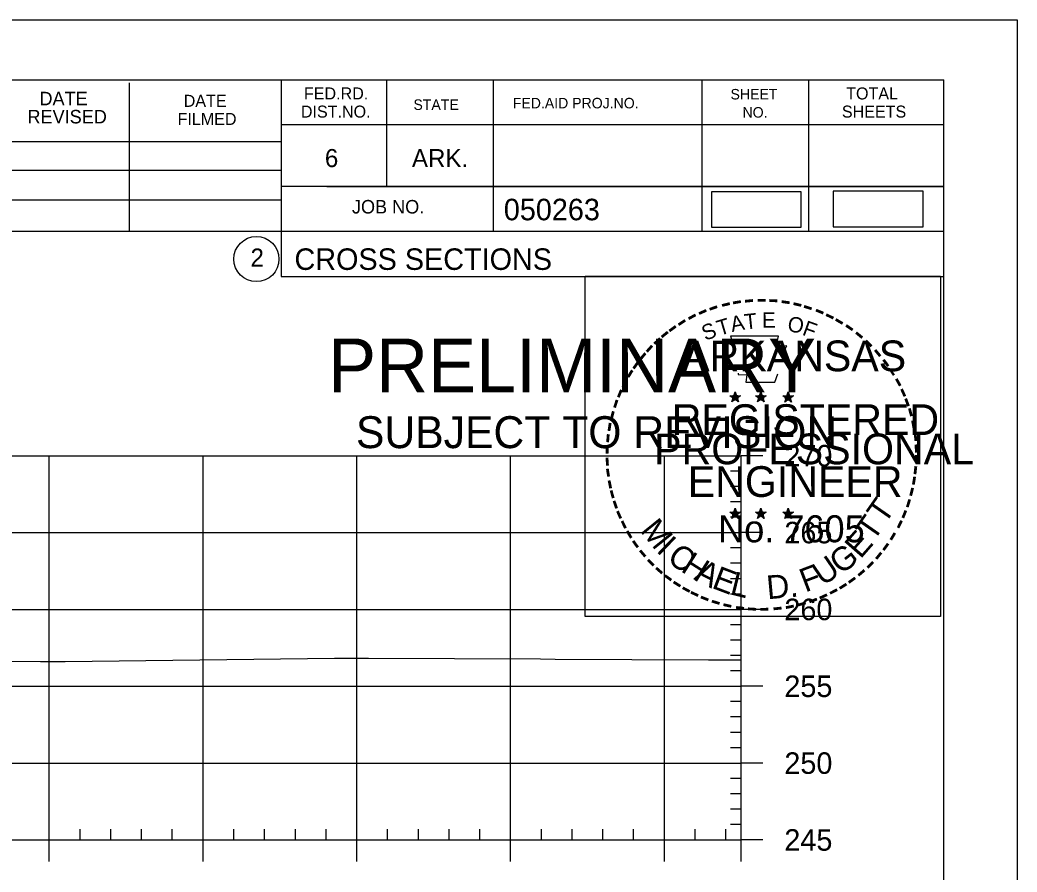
# Model space of a CAD drawing. Extents: x 1365647 to 1367999, y 387113 to 400173.
# Drawn here: x 1365992.2 to 1366057, y 387317.3 to 387372.7 of the extents above; entities that cross this region are included whole.
import ezdxf

# ---------------------------------------------------------------- set-up
doc = ezdxf.new("R2010")
doc.units = 0
for name, color, linetype in [('R_Axis', 7, 'Continuous'), ('R_Axis Annot', 7, 'Continuous'), ('R_Border', 7, 'Continuous'), ('R_Border PE', 7, 'Continuous'), ('R_Border Prem', 7, 'Continuous'), ('R_Detour', 7, 'Continuous'), ('R_Exist Surface', 7, 'Continuous'), ('R_Grid', 7, 'Continuous'), ('R_No Plot', 7, 'Continuous')]:
    doc.layers.add(name, color=color, linetype=linetype)

msp = doc.modelspace()

# ---------------------------------------------------------------- linework, layer by layer
at = {"layer": 'R_Axis'}
for p, q in [((1366039.095, 387319.379), (1366039.095, 387344.379)), ((1366040.495, 387344.379), (1366039.095, 387344.379)), ((1366039.095, 387343.379), (1366038.395, 387343.379)), ((1366039.095, 387342.379), (1366038.395, 387342.379)), ((1366039.095, 387341.379), (1366038.395, 387341.379)), ((1366039.095, 387340.379), (1366038.395, 387340.379)), ((1366040.495, 387339.379), (1366039.095, 387339.379)), ((1366039.095, 387338.379), (1366038.395, 387338.379)), ((1366039.095, 387337.379), (1366038.395, 387337.379)), ((1366039.095, 387336.379), (1366038.395, 387336.379)), ((1366039.095, 387335.379), (1366038.395, 387335.379)), ((1366040.495, 387334.379), (1366039.095, 387334.379)), ((1366039.095, 387333.379), (1366038.395, 387333.379)), ((1366039.095, 387332.379), (1366038.395, 387332.379)), ((1366039.095, 387331.379), (1366038.395, 387331.379)), ((1366039.095, 387330.379), (1366038.395, 387330.379)), ((1366040.495, 387329.379), (1366039.095, 387329.379)), ((1366039.095, 387328.379), (1366038.395, 387328.379)), ((1366039.095, 387327.379), (1366038.395, 387327.379)), ((1366039.095, 387326.379), (1366038.395, 387326.379)), ((1366039.095, 387325.379), (1366038.395, 387325.379)), ((1366040.495, 387324.379), (1366039.095, 387324.379)), ((1366039.095, 387323.379), (1366038.395, 387323.379)), ((1366039.095, 387322.379), (1366038.395, 387322.379)), ((1366039.095, 387321.379), (1366038.395, 387321.379)), ((1365996.095, 387319.379), (1365996.095, 387320.079)), ((1365998.095, 387319.379), (1365998.095, 387320.079)), ((1366000.095, 387319.379), (1366000.095, 387320.079)), ((1366002.095, 387319.379), (1366002.095, 387320.079)), ((1366006.095, 387319.379), (1366006.095, 387320.079)), ((1366008.095, 387319.379), (1366008.095, 387320.079)), ((1366010.095, 387319.379), (1366010.095, 387320.079)), ((1366012.095, 387319.379), (1366012.095, 387320.079)), ((1366016.095, 387319.379), (1366016.095, 387320.079)), ((1366018.095, 387319.379), (1366018.095, 387320.079)), ((1366020.095, 387319.379), (1366020.095, 387320.079)), ((1366022.095, 387319.379), (1366022.095, 387320.079)), ((1366026.095, 387319.379), (1366026.095, 387320.079)), ((1366028.095, 387319.379), (1366028.095, 387320.079)), ((1366030.095, 387319.379), (1366030.095, 387320.079)), ((1366032.095, 387319.379), (1366032.095, 387320.079)), ((1366036.095, 387319.379), (1366036.095, 387320.079)), ((1366038.095, 387319.379), (1366038.095, 387320.079)), ((1366039.095, 387320.379), (1366038.395, 387320.379)), ((1365749.095, 387319.379), (1366039.095, 387319.379)), ((1365994.095, 387317.979), (1365994.095, 387319.379)), ((1366004.095, 387317.979), (1366004.095, 387319.379)), ((1366014.095, 387317.979), (1366014.095, 387319.379)), ((1366024.095, 387317.979), (1366024.095, 387319.379)), ((1366034.095, 387317.979), (1366034.095, 387319.379)), ((1366039.095, 387317.979), (1366039.095, 387319.379)), ((1366040.495, 387319.379), (1366039.095, 387319.379))]:
    msp.add_line(p, q, dxfattribs=at)
at = {"layer": 'R_Border'}
for p, q in [((1365736.095, 387368.839), (1366052.275, 387368.839)), ((1366009.175, 387368.839), (1366009.175, 387356.039)), ((1366016.015, 387368.839), (1366016.015, 387361.899)), ((1366022.955, 387368.839), (1366022.955, 387358.959)), ((1366036.535, 387368.839), (1366036.535, 387358.959)), ((1366043.475, 387368.839), (1366043.475, 387358.959)), ((1366052.275, 387163.379), (1366052.275, 387368.839)), ((1365999.315, 387358.959), (1365999.315, 387368.639)), ((1366052.275, 387365.899), (1366009.175, 387365.899)), ((1366052.275, 387365.919), (1366052.275, 387365.919)), ((1365970.015, 387364.819), (1366009.175, 387364.819)), ((1365970.015, 387362.959), (1366009.175, 387362.959)), ((1366052.275, 387361.899), (1366009.175, 387361.899)), ((1366012.135, 387361.899), (1366052.275, 387361.899)), ((1365970.015, 387361.019), (1366009.175, 387361.019)), ((1366052.275, 387358.959), (1365970.015, 387358.959)), ((1366009.175, 387356.039), (1366052.275, 387356.039))]:
    msp.add_line(p, q, dxfattribs=at)
msp.add_circle((1366007.562, 387357.174), 1.467, dxfattribs=at)
at = {"layer": 'R_Border PE'}
for p, q in [((1366038.356, 387348.285), (1366038.705, 387348.174)), ((1366038.356, 387348.285), (1366038.609, 387348.24)), ((1366038.356, 387348.285), (1366038.593, 387348.163)), ((1366038.489, 387347.877), (1366038.705, 387348.174)), ((1366038.489, 387347.877), (1366038.615, 387348.121)), ((1366038.489, 387347.877), (1366038.703, 387348.094)), ((1366038.705, 387348.539), (1366038.664, 387348.287)), ((1366038.918, 387347.877), (1366038.703, 387348.091)), ((1366038.705, 387348.174), (1366038.705, 387348.539)), ((1366038.705, 387348.539), (1366038.754, 387348.289)), ((1366039.052, 387348.285), (1366038.705, 387348.174)), ((1366038.918, 387347.877), (1366038.705, 387348.174)), ((1366039.052, 387348.285), (1366038.766, 387348.236)), ((1366038.918, 387347.877), (1366038.781, 387348.168)), ((1366039.052, 387348.285), (1366038.848, 387348.183)), ((1366040.026, 387348.285), (1366040.375, 387348.174)), ((1366040.026, 387348.285), (1366040.279, 387348.24)), ((1366040.026, 387348.285), (1366040.263, 387348.163)), ((1366040.159, 387347.877), (1366040.375, 387348.174)), ((1366040.159, 387347.877), (1366040.285, 387348.121)), ((1366040.159, 387347.877), (1366040.373, 387348.094)), ((1366040.375, 387348.539), (1366040.334, 387348.287)), ((1366040.588, 387347.877), (1366040.373, 387348.091)), ((1366040.375, 387348.174), (1366040.375, 387348.539)), ((1366040.375, 387348.539), (1366040.424, 387348.289)), ((1366040.722, 387348.285), (1366040.375, 387348.174)), ((1366040.588, 387347.877), (1366040.375, 387348.174)), ((1366040.722, 387348.285), (1366040.436, 387348.236)), ((1366040.588, 387347.877), (1366040.451, 387348.168)), ((1366040.722, 387348.285), (1366040.518, 387348.183)), ((1366041.79, 387348.273), (1366042.139, 387348.162)), ((1366041.79, 387348.273), (1366042.043, 387348.228)), ((1366041.79, 387348.273), (1366042.027, 387348.151)), ((1366041.923, 387347.865), (1366042.139, 387348.162)), ((1366041.923, 387347.865), (1366042.049, 387348.109)), ((1366041.923, 387347.865), (1366042.137, 387348.082)), ((1366042.139, 387348.527), (1366042.098, 387348.275)), ((1366042.352, 387347.865), (1366042.137, 387348.079)), ((1366042.139, 387348.162), (1366042.139, 387348.527)), ((1366042.139, 387348.527), (1366042.188, 387348.277)), ((1366042.486, 387348.273), (1366042.139, 387348.162)), ((1366042.352, 387347.865), (1366042.139, 387348.162)), ((1366042.486, 387348.273), (1366042.2, 387348.224)), ((1366042.352, 387347.865), (1366042.215, 387348.156)), ((1366042.486, 387348.273), (1366042.282, 387348.171)), ((1366038.701, 387340.966), (1366038.66, 387340.714)), ((1366038.701, 387340.601), (1366038.701, 387340.966)), ((1366038.701, 387340.966), (1366038.75, 387340.716)), ((1366040.37, 387340.966), (1366040.329, 387340.714)), ((1366040.37, 387340.601), (1366040.37, 387340.966)), ((1366040.37, 387340.966), (1366040.419, 387340.716)), ((1366042.137, 387340.956), (1366042.096, 387340.704)), ((1366042.137, 387340.591), (1366042.137, 387340.956)), ((1366042.137, 387340.956), (1366042.186, 387340.706)), ((1366038.352, 387340.712), (1366038.701, 387340.601)), ((1366038.352, 387340.712), (1366038.605, 387340.667)), ((1366038.352, 387340.712), (1366038.589, 387340.59)), ((1366038.485, 387340.304), (1366038.701, 387340.601)), ((1366038.485, 387340.304), (1366038.611, 387340.548)), ((1366038.485, 387340.304), (1366038.699, 387340.521)), ((1366038.914, 387340.304), (1366038.699, 387340.518)), ((1366039.048, 387340.712), (1366038.701, 387340.601)), ((1366038.914, 387340.304), (1366038.701, 387340.601)), ((1366039.048, 387340.712), (1366038.762, 387340.663)), ((1366038.914, 387340.304), (1366038.777, 387340.595)), ((1366039.048, 387340.712), (1366038.844, 387340.61)), ((1366040.021, 387340.712), (1366040.37, 387340.601)), ((1366040.021, 387340.712), (1366040.274, 387340.667)), ((1366040.021, 387340.712), (1366040.258, 387340.59)), ((1366040.154, 387340.304), (1366040.37, 387340.601)), ((1366040.154, 387340.304), (1366040.28, 387340.548)), ((1366040.154, 387340.304), (1366040.368, 387340.521)), ((1366040.583, 387340.304), (1366040.368, 387340.518)), ((1366040.717, 387340.712), (1366040.37, 387340.601)), ((1366040.583, 387340.304), (1366040.37, 387340.601)), ((1366040.717, 387340.712), (1366040.431, 387340.663)), ((1366040.583, 387340.304), (1366040.446, 387340.595)), ((1366040.717, 387340.712), (1366040.513, 387340.61)), ((1366041.788, 387340.702), (1366042.137, 387340.591)), ((1366041.788, 387340.702), (1366042.041, 387340.657)), ((1366041.788, 387340.702), (1366042.025, 387340.58)), ((1366041.921, 387340.294), (1366042.137, 387340.591)), ((1366041.921, 387340.294), (1366042.047, 387340.538)), ((1366041.921, 387340.294), (1366042.135, 387340.511)), ((1366042.35, 387340.294), (1366042.135, 387340.508)), ((1366042.484, 387340.702), (1366042.137, 387340.591)), ((1366042.35, 387340.294), (1366042.137, 387340.591)), ((1366042.484, 387340.702), (1366042.198, 387340.653)), ((1366042.35, 387340.294), (1366042.213, 387340.585)), ((1366042.484, 387340.702), (1366042.28, 387340.6))]:
    msp.add_line(p, q, dxfattribs=at)
for points in [[(1366038.397, 387352.163), (1366038.666, 387351.336)], [(1366041.908, 387351.241), (1366042.05, 387351.525), (1366041.365, 387351.501), (1366041.513, 387352.163), (1366038.397, 387352.163)], [(1366038.889, 387349.74), (1366038.889, 387349.653), (1366039.452, 387349.634), (1366039.398, 387349.161), (1366041.268, 387349.161), (1366041.469, 387349.697)], [(1366038.705, 387348.539), (1366038.918, 387347.877), (1366038.356, 387348.285), (1366039.052, 387348.285), (1366038.489, 387347.877), (1366038.705, 387348.539)], [(1366040.375, 387348.539), (1366040.588, 387347.877), (1366040.026, 387348.285), (1366040.722, 387348.285), (1366040.159, 387347.877), (1366040.375, 387348.539)], [(1366042.139, 387348.527), (1366042.352, 387347.865), (1366041.79, 387348.273), (1366042.486, 387348.273), (1366041.923, 387347.865), (1366042.139, 387348.527)], [(1366038.701, 387340.966), (1366038.914, 387340.304), (1366038.352, 387340.712), (1366039.048, 387340.712), (1366038.485, 387340.304), (1366038.701, 387340.966)], [(1366040.37, 387340.966), (1366040.583, 387340.304), (1366040.021, 387340.712), (1366040.717, 387340.712), (1366040.154, 387340.304), (1366040.37, 387340.966)], [(1366042.137, 387340.956), (1366042.35, 387340.294), (1366041.788, 387340.702), (1366042.484, 387340.702), (1366041.921, 387340.294), (1366042.137, 387340.956)]]:
    msp.add_lwpolyline(points, dxfattribs=at)
for centre, radius in [((1366038.704, 387348.174), 0.172), ((1366038.704, 387348.174), 0.145), ((1366038.704, 387348.174), 0.116), ((1366038.704, 387348.174), 0.0991), ((1366038.704, 387348.174), 0.0747), ((1366038.704, 387348.174), 0.0495), ((1366038.704, 387348.174), 0.0296), ((1366040.374, 387348.174), 0.172), ((1366040.374, 387348.174), 0.145), ((1366040.374, 387348.174), 0.116), ((1366040.374, 387348.174), 0.0991), ((1366040.374, 387348.174), 0.0747), ((1366040.374, 387348.174), 0.0495), ((1366040.374, 387348.174), 0.0296), ((1366042.138, 387348.162), 0.172), ((1366042.138, 387348.162), 0.145), ((1366042.138, 387348.162), 0.116), ((1366042.138, 387348.162), 0.0991), ((1366042.138, 387348.162), 0.0747), ((1366042.138, 387348.162), 0.0495), ((1366042.138, 387348.162), 0.0296), ((1366038.7, 387340.601), 0.172), ((1366038.7, 387340.601), 0.145), ((1366038.7, 387340.601), 0.116), ((1366038.7, 387340.601), 0.0991), ((1366038.7, 387340.601), 0.0747), ((1366038.7, 387340.601), 0.0495), ((1366038.7, 387340.601), 0.0296), ((1366040.369, 387340.601), 0.172), ((1366040.369, 387340.601), 0.145), ((1366040.369, 387340.601), 0.116), ((1366040.369, 387340.601), 0.0991), ((1366040.369, 387340.601), 0.0747), ((1366040.369, 387340.601), 0.0495), ((1366040.369, 387340.601), 0.0296), ((1366042.136, 387340.591), 0.172), ((1366042.136, 387340.591), 0.145), ((1366042.136, 387340.591), 0.116), ((1366042.136, 387340.591), 0.0991), ((1366042.136, 387340.591), 0.0747), ((1366042.136, 387340.591), 0.0495), ((1366042.136, 387340.591), 0.0296)]:
    msp.add_circle(centre, radius, dxfattribs=at)
at = {"layer": 'R_Detour'}
for points in [[(1366037.165, 387359.249), (1366042.998, 387359.249), (1366042.998, 387361.559), (1366037.165, 387361.559)], [(1366045.079, 387359.28), (1366050.912, 387359.28), (1366050.912, 387361.591), (1366045.079, 387361.591)]]:
    msp.add_lwpolyline(points, close=True, dxfattribs=at)
at = {"layer": 'R_Exist Surface'}
msp.add_lwpolyline([(1365939.992, 387332.412), (1365941.84, 387332.154), (1365943.802, 387331.959), (1365948.828, 387331.523), (1365959.741, 387331.401), (1365967.901, 387331.317), (1365979.854, 387331.115), (1365980.51, 387331.11), (1365983.822, 387331.048), (1365993.529, 387330.997), (1365995.126, 387330.995), (1366012.64, 387331.215), (1366014.846, 387331.21), (1366026.045, 387331.154), (1366026.99, 387331.151), (1366036.953, 387331.1), (1366039.095, 387331.097)], dxfattribs=at)
at = {"layer": 'R_Grid'}
for p, q in [((1365749.095, 387344.379), (1366039.095, 387344.379)), ((1365994.095, 387319.379), (1365994.095, 387344.379)), ((1366004.095, 387319.379), (1366004.095, 387344.379)), ((1366014.095, 387319.379), (1366014.095, 387344.379)), ((1366024.095, 387319.379), (1366024.095, 387344.379)), ((1366034.095, 387319.379), (1366034.095, 387344.379)), ((1366039.095, 387319.379), (1366039.095, 387344.379)), ((1365749.095, 387339.379), (1366039.095, 387339.379)), ((1365749.095, 387334.379), (1366039.095, 387334.379)), ((1365749.095, 387329.379), (1366039.095, 387329.379)), ((1365749.095, 387324.379), (1366039.095, 387324.379)), ((1365749.095, 387319.379), (1366039.095, 387319.379))]:
    msp.add_line(p, q, dxfattribs=at)
at = {"layer": 'R_No Plot'}
msp.add_line((1365723.694, 387372.733), (1366057.027, 387372.733), dxfattribs=at)
for points in [[(1365723.687, 387372.733), (1366057.027, 387372.733), (1366057.027, 387159.396), (1365723.687, 387159.396)], [(1366028.946, 387356.071), (1366052.044, 387356.071), (1366052.044, 387333.921), (1366028.946, 387333.921)]]:
    msp.add_lwpolyline(points, close=True, dxfattribs=at)

# ---------------------------------------------------------------- texts
at = {"layer": 'R_Axis Annot'}
for s, p in [('270', (1366041.895, 387343.679)), ('265', (1366041.895, 387338.679)), ('260', (1366041.895, 387333.679)), ('255', (1366041.895, 387328.679)), ('250', (1366041.895, 387323.679)), ('245', (1366041.895, 387318.679))]:
    msp.add_text(s, height=1.4, dxfattribs=at).set_placement(p)
at = {"layer": 'R_Border'}
for s, height, p in [('DATE', 0.8792, (1365993.455, 387367.179)), ('FED.RD.', 0.7819, (1366010.655, 387367.559)), ('SHEET', 0.684, (1366038.395, 387367.559)), ('TOTAL', 0.7819, (1366045.915, 387367.559)), ('DATE', 0.7819, (1366002.835, 387367.079)), ('STATE', 0.684, (1366017.775, 387366.879)), ('FED.AID PROJ.NO.', 0.684, (1366024.235, 387366.979)), ('REVISED', 0.8792, (1365992.675, 387365.999)), ('DIST.NO.', 0.7819, (1366010.455, 387366.379)), ('NO.', 0.684, (1366039.175, 387366.379)), ('SHEETS', 0.7819, (1366045.635, 387366.379)), ('FILMED', 0.7819, (1366002.435, 387365.899)), ('6', 1.172, (1366012.015, 387363.159)), ('ARK.', 1.1723, (1366017.675, 387363.159)), ('JOB NO.', 0.8792, (1366013.775, 387360.139)), ('050263', 1.4, (1366023.651, 387359.698)), ('2', 1.172, (1366007.179, 387356.688)), ('CROSS SECTIONS', 1.4, (1366010.038, 387356.469))]:
    msp.add_text(s, height=height, rotation=360, dxfattribs=at).set_placement(p)
at = {"layer": 'R_Border PE'}
for s, height, rotation, p in [('-', 1.6, 10.21935, (1366038.573, 387353.693)), ('-', 1.6, 5.89682, (1366039.302, 387353.803)), ('-', 1.6, 0.18623, (1366040.074, 387353.875)), ('-', 1.6, 357.74304, (1366040.797, 387353.862)), ('-', 1.6, 352.16172, (1366041.541, 387353.806)), ('-', 1.6, 24.30721, (1366036.511, 387353.021)), ('-', 1.6, 19.17608, (1366037.145, 387353.29)), ('-', 1.6, 13.63015, (1366037.895, 387353.531)), ('-', 1.6, 347.20489, (1366042.26, 387353.692)), ('-', 1.6, 342.3362, (1366042.895, 387353.537)), ('-', 1.6, 337.85509, (1366043.63, 387353.314)), ('-', 1.6, 34.06357, (1366035.281, 387352.334)), ('-', 1.6, 28.79182, (1366035.878, 387352.704)), ('T', 1, 16.4036, (1366037.666, 387352.172)), ('A', 1, 11.21318, (1366038.492, 387352.423)), ('T', 1, 6.02276, (1366039.341, 387352.589)), ('E', 1, 0.83234, (1366040.446, 387352.699)), ('O', 1, 350.4515, (1366042.05, 387352.489)), ('F', 1, 340.07066, (1366043.004, 387352.261)), ('-', 1.6, 334.12109, (1366044.261, 387353.043)), ('-', 1.6, 329.64089, (1366044.84, 387352.76)), ('-', 1.6, 38.95066, (1366034.227, 387351.561)), ('-', 1.6, 36.23174, (1366034.703, 387351.939)), ('S', 1, 21.59401, (1366036.752, 387351.841)), ('-', 1.6, 325.86266, (1366045.483, 387352.399)), ('-', 1.6, 42.96224, (1366033.794, 387351.144)), ('ARKANSAS', 2, 360, (1366035.25, 387349.875)), ('-', 1.6, 320.52971, (1366046.093, 387351.973)), ('-', 1.6, 315.57859, (1366046.692, 387351.485)), ('-', 1.6, 48.42305, (1366033.346, 387350.666)), ('-', 1.6, 309.87973, (1366047.261, 387350.935)), ('-', 1.6, 54.23247, (1366032.53, 387349.613)), ('-', 1.6, 50.61417, (1366032.943, 387350.18)), ('-', 1.6, 306.65218, (1366047.786, 387350.333)), ('-', 1.6, 58.07063, (1366032.205, 387349.086)), ('-', 1.4, 303.67529, (1366048.272, 387349.765)), ('-', 1.6, 62.87135, (1366031.892, 387348.472)), ('-', 1.6, 299.66835, (1366048.591, 387349.158)), ('-', 1.6, 67.77427, (1366031.633, 387347.861)), ('-', 1.6, 294.66279, (1366048.915, 387348.546)), ('-', 1.6, 72.39447, (1366031.414, 387347.231)), ('DWB', 0.01, 360, (1366038.691, 387348.169)), ('DWB', 0.01, 360, (1366040.361, 387348.169)), ('DWB', 0.01, 360, (1366042.125, 387348.157)), ('-', 1.6, 290.57283, (1366049.172, 387347.969)), ('-', 1.6, 75.46096, (1366031.217, 387346.517)), ('REGISTERED', 2, 360, (1366034.572, 387345.726)), ('-', 1.6, 285.12326, (1366049.406, 387347.389)), ('-', 1.6, 280.54934, (1366049.606, 387346.647)), ('-', 1.6, 81.20126, (1366031.085, 387345.804)), ('-', 1.6, 85.18634, (1366031.009, 387345.113)), ('PROFESSIONAL', 2, 360, (1366033.424, 387343.822)), ('-', 1.6, 276.59616, (1366049.768, 387345.879)), ('-', 1.6, 89.06224, (1366030.984, 387344.412)), ('-', 1.6, 274.33011, (1366049.828, 387345.157)), ('-', 1.6, 94.19588, (1366031.019, 387343.687)), ('-', 1.6, 269.94067, (1366049.862, 387344.525)), ('-', 1.6, 98.94793, (1366031.091, 387343.02)), ('ENGINEER', 2, 360, (1366035.611, 387341.697)), ('-', 1.6, 263.5172, (1366049.843, 387343.859)), ('-', 1.6, 101.71495, (1366031.226, 387342.287)), ('-', 1.6, 260.99529, (1366049.772, 387343.205)), ('-', 1.6, 105.45785, (1366031.388, 387341.692)), ('-', 1.6, 255.7626, (1366049.662, 387342.527)), ('-', 1.6, 109.08742, (1366031.603, 387341.061)), ('T', 1.54, 55.05496, (1366048.42, 387339.866)), ('-', 1.6, 252.86809, (1366049.481, 387341.807)), ('-', 1.6, 114.06432, (1366031.857, 387340.465)), ('-', 1.6, 247.88866, (1366049.258, 387341.134)), ('-', 1.6, 115.72885, (1366032.162, 387339.847)), ('M', 1.54, 308.91747, (1366032.472, 387339.492)), ('No. 7605', 1.757, 360, (1366037.585, 387338.746)), ('DWB', 0.01, 360, (1366038.686, 387340.597)), ('DWB', 0.01, 360, (1366040.355, 387340.595)), ('DWB', 0.01, 360, (1366042.122, 387340.586)), ('T', 1.54, 55.05496, (1366047.689, 387338.746)), ('-', 1.6, 244.61971, (1366048.996, 387340.505)), ('-', 1.6, 120.44712, (1366032.519, 387339.261)), ('E', 1.54, 48.73133, (1366046.843, 387337.619)), ('-', 1.6, 125.89344, (1366032.922, 387338.7)), ('I', 1.54, 316.46364, (1366033.514, 387338.172)), ('-', 1.6, 239.07125, (1366048.602, 387339.753)), ('-', 1.6, 130.71812, (1366033.384, 387338.148)), ('C', 1.54, 324.01974, (1366034.187, 387337.549)), ('G', 1.54, 38.21734, (1366045.59, 387336.599)), ('-', 1.6, 233.84524, (1366048.2, 387339.1)), ('-', 1.6, 134.22381, (1366033.901, 387337.603)), ('H', 1.54, 327.53419, (1366035.097, 387336.894)), ('U', 1.54, 34.40523, (1366044.391, 387335.866)), ('-', 1.6, 231.25377, (1366047.77, 387338.534)), ('-', 1.6, 138.93382, (1366034.426, 387337.139)), ('A', 1.54, 332.55127, (1366035.951, 387336.357)), ('E', 1.54, 339.20679, (1366037.109, 387335.795)), ('F', 1.54, 20.82016, (1366043.254, 387335.472)), ('-', 1.6, 221.08509, (1366046.769, 387337.461)), ('-', 1.6, 225.76533, (1366047.291, 387337.97)), ('-', 1.6, 144.64634, (1366034.982, 387336.733)), ('L', 1.54, 346.2929, (1366038.301, 387335.371)), ('D.', 1.54, 5.26016, (1366040.804, 387335.034)), ('-', 1.6, 215.73633, (1366046.22, 387336.989)), ('-', 1.6, 148.08978, (1366035.543, 387336.362)), ('-', 1.6, 151.57039, (1366036.122, 387336.037)), ('-', 1.6, 207.35684, (1366045.128, 387336.256)), ('-', 1.6, 212.24909, (1366045.686, 387336.602)), ('-', 1.6, 154.60019, (1366036.644, 387335.79)), ('-', 1.6, 158.56121, (1366037.268, 387335.536)), ('-', 1.6, 162.79826, (1366037.955, 387335.323)), ('-', 1.6, 200.71842, (1366043.885, 387335.664)), ('-', 1.6, 204.25161, (1366044.504, 387335.937)), ('-', 1.6, 167.55551, (1366038.67, 387335.159)), ('-', 1.6, 173.11546, (1366039.442, 387335.049)), ('-', 1.6, 176.51827, (1366040.19, 387334.996)), ('-', 1.6, 181.59176, (1366040.934, 387335.015)), ('-', 1.6, 185.81666, (1366041.743, 387335.091)), ('-', 1.6, 191.28576, (1366042.479, 387335.223)), ('-', 1.6, 195.47429, (1366043.208, 387335.422))]:
    msp.add_text(s, height=height, rotation=rotation, dxfattribs=at).set_placement(p)
at = {"layer": 'R_Border Prem'}
for s, height, p in [('PRELIMINARY', 3.5, (1366012.226, 387348.502)), ('DWB', 0.01, (1366012.973, 387350.351)), ('SUBJECT TO REVISION', 2.07511, (1366014.035, 387344.873))]:
    msp.add_text(s, height=height, rotation=360, dxfattribs=at).set_placement(p)

doc.saveas('drawing.dxf')
